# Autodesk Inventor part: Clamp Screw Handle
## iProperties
Shininess: 77.0
Length Units: 11269
Angle Units: 11279
Time Units: 11290
Mass Units: 11283
Length Display Precision: 3
Angle Display Precision: 2
Compacted: True
Created: 2002-02
Part Number: Clamp Screw Handle
Document SubType Name: Modeling
Designer: ***
Density: 0.0
Volumn: 0.0
Area: 0.0
PropertySet Name: Model Information
Control State: 0
Master: False
Checked Out: False
Author: ***
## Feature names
1. Revolution1
